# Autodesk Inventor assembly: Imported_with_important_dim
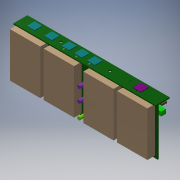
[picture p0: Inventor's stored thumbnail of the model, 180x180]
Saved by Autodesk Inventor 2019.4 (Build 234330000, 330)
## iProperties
Created: 2019-11
Part Number: Imported_with_important_dim
Document SubType Name: Assembly
Designer: Willist
Author: Willist
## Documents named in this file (3)
- D:\Biblioteki\Dokumenty\,Studia\StudiaMagisterskie\Semestry\Semestr2\ProjektGupowy\GIT\Projekt-Grupowy-Minutnik\Minutnix\3d\Imported_with_important_dim.iam
- D:\Biblioteki\Dokumenty\,Studia\StudiaMagisterskie\Semestry\Semestr2\ProjektGupowy\GIT\Projekt-Grupowy-Minutnik\Minutnix\3d\Ekspander.brd.iam
- D:\Biblioteki\Dokumenty\,Studia\StudiaMagisterskie\Semestry\Semestr2\ProjektGupowy\GIT\Projekt-Grupowy-Minutnik\Minutnix\3d\MainBoard.brd2.iam
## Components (2 placed, 2 different names)
1. Ekspander.brd:1 [sub-assembly]
2. MainBoard.brd:1 [sub-assembly]
